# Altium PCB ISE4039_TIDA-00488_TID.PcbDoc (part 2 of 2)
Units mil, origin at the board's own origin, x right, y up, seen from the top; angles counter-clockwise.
Board outline 3000 x 2000 mil, 4 copper layers (Layer 1 - Top Layer, Layer 2 - GND, Layer 3 - PWR, Layer 4 - Bottom Layer), stack 32.634 mil thick; 131 components, 56 nets, 369 pads, 363 vias.
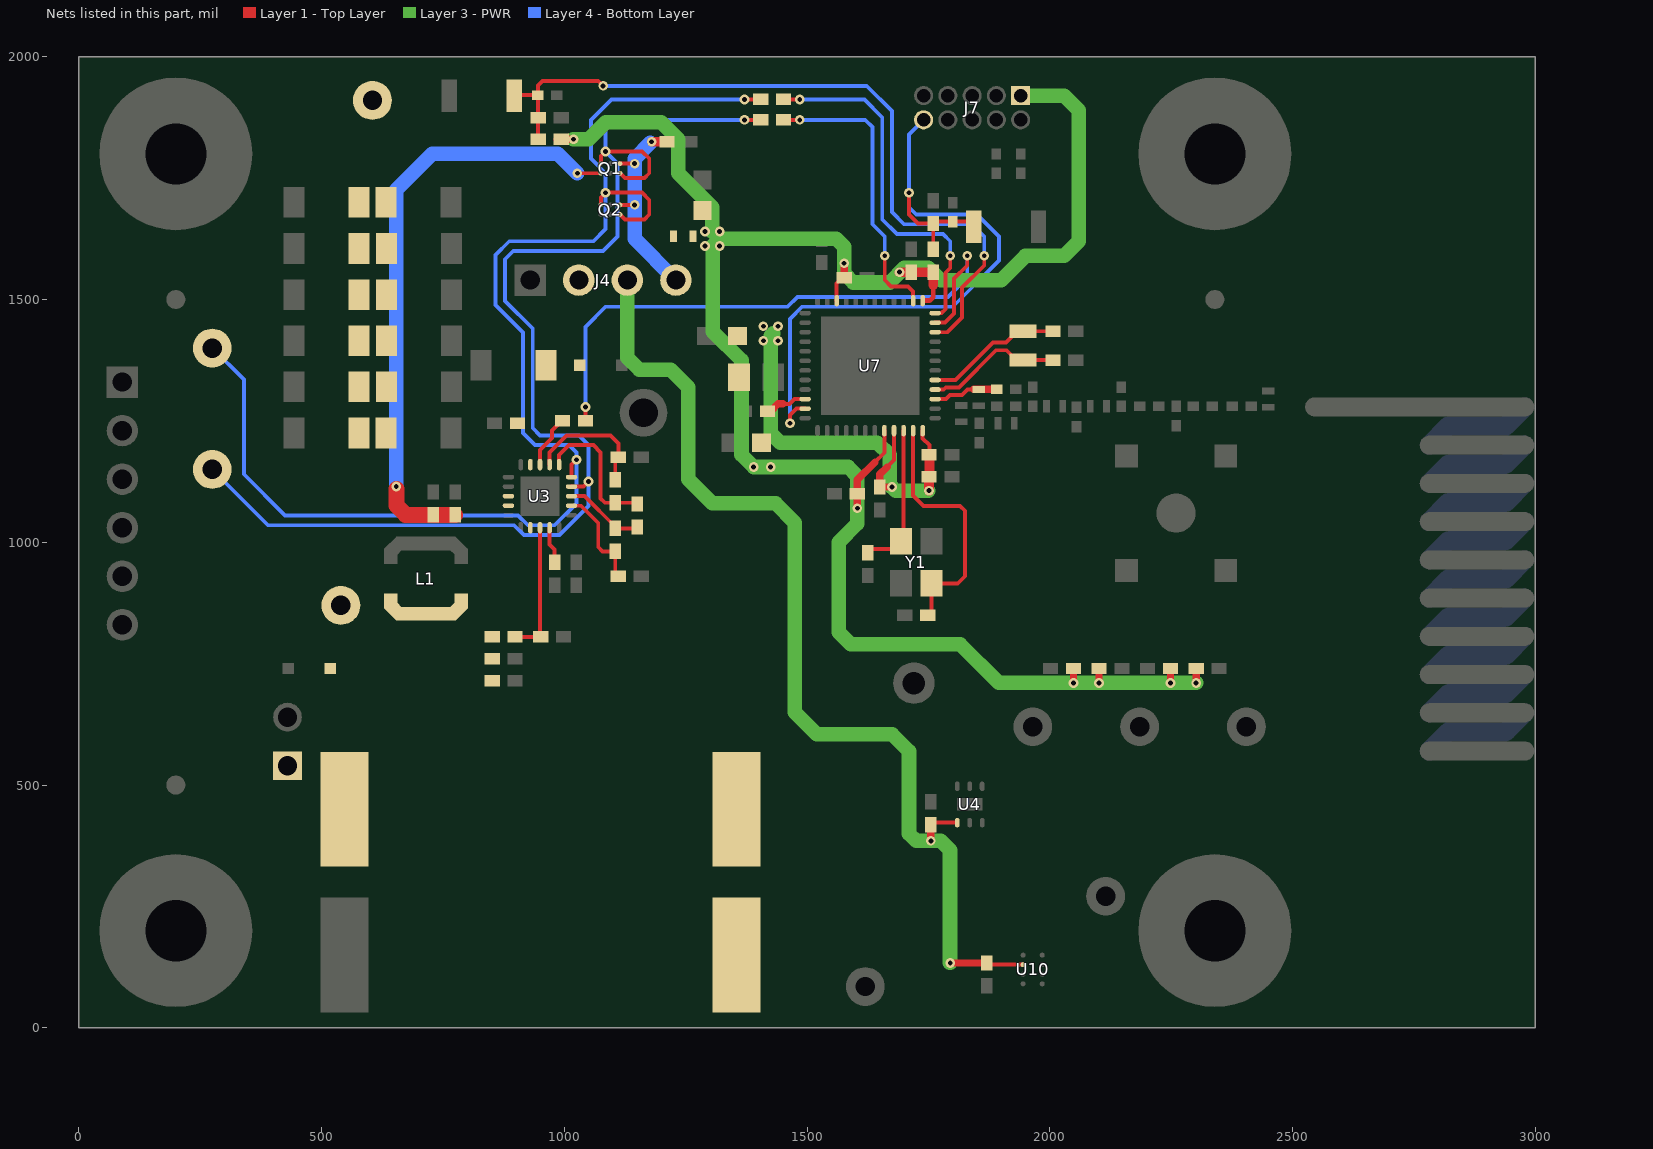
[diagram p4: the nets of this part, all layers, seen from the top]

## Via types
v1: diameter 20, hole 10, Layer 1 - Top Layer to Layer 4 - Bottom Layer, tented both sides, 323 vias
v2: diameter 19.68, hole 7.87, Layer 1 - Top Layer to Layer 4 - Bottom Layer, tented both sides, 21 vias
v3: diameter 39.37, hole 14.96, Layer 1 - Top Layer to Layer 4 - Bottom Layer, 19 vias

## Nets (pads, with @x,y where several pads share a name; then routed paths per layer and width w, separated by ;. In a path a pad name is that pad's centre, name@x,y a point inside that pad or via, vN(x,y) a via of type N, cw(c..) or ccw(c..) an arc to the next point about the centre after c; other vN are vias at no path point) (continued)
NetR1_1: R1.1 R2.2 U3.3 | length 268.3
  Layer 1 - Top Layer w8: R1.1@898.62,805 R2.2@951.38,805 R2.2@950,806.38 ; R2.2@950,816.38 U3.3@950,1030
NetR3_2: R3.2 U7.12 | length 756
  Layer 1 - Top Layer w8: R3.2@1451.62,1912 v1(1485,1912) ; U7.12@1763.74,1472.03 1777.03,1472.03 1785,1480 1785,1555 1795,1565 v1(1795,1590)
  Layer 4 - Bottom Layer w8: v1(1485,1912) 1618,1912 1655,1875 1655,1665 1685,1635 1780,1635 1795,1620 v1(1795,1590)
NetR5_2: R5.2 U3.13 | length 110.1
  Layer 1 - Top Layer w8: U3.13@950,1159.92 950,1190 975,1215 975,1230 995,1250 R5.2@996.38,1250
NetR11_2: R11.2 U7.14 | length 602
  Layer 1 - Top Layer w8: R11.2@1451.62,1870 v1(1485,1870) ; v1(1660,1590) 1660,1540 1673,1527 1708,1527 1718.46,1516.54 U7.14@1718.46,1497.62
  Layer 4 - Bottom Layer w8: v1(1485,1870) 1620,1870 1635,1855 1635,1655 1660,1630 v1(1660,1590)
NetU1_2: U1.2 U2.1
NRESET: C32.2 J7.10 R13.1 S2.2 U6.1 U7.35 | length 1429.5
  Layer 1 - Top Layer w8: v1(1465,1245) 1465,1262 1478.18,1275.18 U7.35@1496.02,1275.18 ; v1(1710,1720) 1710,1675 1728.62,1656.38 C32.2@1760,1656.38 1763.94,1660.31 U6.1@1800,1660.32 1832.76,1660.32 S2.2@1842.76,1650.32 ; R13.1@1760,1608.62 C32.2@1760,1646.38
  Layer 4 - Bottom Layer w8: v1(1465,1245) 1465,1460 1490,1485 1800,1485 1895,1580 1895,1630 1850,1675 1725,1675 1710,1690 v1(1710,1720) 1710,1840 J7.10@1740,1870
OK_HYST: R7.1 R9.2 U3.11 | length 294.6
  Layer 1 - Top Layer w8: U3.11@989.37,1159.92 989.37,1179.37 1010,1200 1060,1200 1075,1185 1075,1090 1083.62,1081.38 R9.2@1105,1081.38 1147.24,1081.38 R7.1@1150,1078.62
OK_PROG: R9.1 R10.2 U3.12 | length 256.5
  Layer 1 - Top Layer w8: U3.12@969.68,1159.92 969.68,1184.68 1005,1220 1095,1220 1111.38,1203.62 R10.2@1111.38,1175 ; R9.1@1105,1128.62 R10.2@1105,1168.62
RX_TX: C42.1 L8.1 U7.3 | length 145.8
  Layer 1 - Top Layer w8: U7.3@1763.74,1294.87 1785.87,1294.87 1794.24,1303.24 1819.16,1303.24 1830.65,1314.73 L8.1@1854,1314.73
  Layer 1 - Top Layer w15: L8.1@1843,1315 C42.1@1890.31,1315
USR_BTN: C31.2 R12.1 S1.2 U5.1 U7.10 | length 1591.5
  Layer 1 - Top Layer w8: S1.2@896.93,1920 897.93,1921 U5.1@945.63,1921 ; R12.1@945.63,1830 945.63,1874 U5.1@945.63,1921 ; v1(1080,1940) 1070,1950 955,1950 945.63,1940.63 U5.1@945.63,1921 ; U7.10@1763.74,1432.66 1789.03,1432.66 1819.5,1463.13 1819.5,1524.5 1865,1570 v1(1865,1590)
  Layer 4 - Bottom Layer w8: v1(1080,1940) 1623,1940 1675,1888 1675,1680 1700,1655 1840,1655 1865,1630 v1(1865,1590)
V_SOLAR: J1.1 U1.1
VB_PRI_ON: Q2.A2 Q2.C1 R3.1 TP5.1 U3.10 | length 2772.8
  Layer 1 - Top Layer w8: U3.10@1014.96,1134.33 1014.96,1159.96 v1(1025,1170) ; Q2.C1@1075.32,1694.84 1075.32,1710.32 v1(1085,1720) 1160,1720 1175,1705 1175,1675 1165,1665 1124.84,1665 Q2.A2@1114.68,1675.16 ; v1(1371,1912) R3.1@1404.38,1912
  Layer 4 - Bottom Layer w8: TP5.1@275,1400 340,1335 340,1140 425,1055 905,1055 925,1035 980,1035 1025,1080 v1(1025,1170) 1025,1185 1010,1200 940,1200 915,1225 915,1431.72 858,1488.72 858,1591.28 886.72,1620 1060,1620 1085,1645 v1(1085,1720) 1085,1760 1055,1790 1055,1870 1097,1912 v1(1371,1912)
VB_SEC_ON: Q1.A2 Q1.C1 R11.1 TP2.1 U3.9 | length 2554.7
  Layer 1 - Top Layer w8: U3.9@1014.96,1114.65 1039.65,1114.65 v1(1050,1125) ; Q1.C1@1075.32,1779.84 1075.32,1795.32 v1(1085,1805) 1160,1805 1175,1790 1175,1760 1165,1750 1124.84,1750 Q1.A2@1114.69,1760.16 ; v1(1371,1870) R11.1@1404.38,1870
  Layer 4 - Bottom Layer w8: TP2.1@275,1150 390,1035 896.72,1035 916.72,1015 990,1015 1050,1075 v1(1050,1125) 1050,1200 1030,1220 950,1220 935,1235 935,1440 878,1497 878,1583 895,1600 1080,1600 1110,1630 1110,1780 v1(1085,1805) 1085,1850 1105,1870 v1(1371,1870)
VBAT_OK: R5.1 U7.11 | length 1244.2
  Layer 1 - Top Layer w8: R5.1@1043.62,1250 v1(1043.62,1278.62) ; U7.11@1763.74,1452.35 1784.35,1452.35 1803,1471 1803,1543 1830,1570 v1(1830,1590)
  Layer 4 - Bottom Layer w8: v1(1043.62,1278.62) 1043.62,1443.62 1085,1485 1460,1485 1480,1505 1790,1505 1830,1545 v1(1830,1590)
VBAT_OV: R6.1 R8.2 U3.7 | length 208.2
  Layer 1 - Top Layer w8: U3.7@1014.96,1075.28 1034.72,1075.28 1070,1040 1070,990 1078.62,981.38 R6.1@1105,981.38 R8.2@1105,931.38
VBAT_PRI: C18.1 C48.1 D2.1 J4.2 U3.14
VBAT_SEC: C6.1 C7.1 C8.1 C9.1 C10.1 C11.1 C12.1 C13.1 C14.1 C15.1 C16.1 C17.1 TP3.1 U3.18
VDD_3P3: C20.2 C43.2 J4.3 L2.2 U4.1 U10.B1 | length 2156.8
  Layer 1 - Top Layer w8: C20.2@1755.6,422.6 U4.1@1809.41,422.6 ; C43.2@1870,133.62 1870,129.69 1870.31,130 U10.B1@1945,130
  Layer 1 - Top Layer w15: v1(1755,385) C20.2@1755,418.38 ; v1(1795,133.62) C43.2@1870,133.62
  Layer 3 - PWR w30: J4.3@1130,1540 1130,1380 1155,1355 1219.4,1355 1255,1319.4 1255,1130 1305,1080 1435,1080 1475,1040 1475,650 1520,605 1675,605 1710,570 1710,400 1725,385 v1(1755,385) 1775,385 1794.51,365.49 v1@1794.51,133.62
VDD_3P3_SW: C19.1 J4.4 Q1.A1 Q2.A1 | length 423.2
  Layer 1 - Top Layer w8: Q2.A1@1114.68,1694.84 v1(1145,1694.84) ; Q1.A1@1114.69,1779.84 v1(1145,1779.84)
  Layer 1 - Top Layer w20: v1(1180,1825) C19.1@1211.38,1825
  Layer 4 - Bottom Layer w30: v1@1177.5,1822.5 1145,1790 v1(1145,1779.84) v1(1145,1694.84) 1145,1625 J4.4@1230,1540
VDDR: C27.1 C28.1 C29.1 C30.1 L3.2 U7.45 U7.48 | length 890.5
  Layer 1 - Top Layer w8: 1665,1155 1679.09,1169.09 U7.45@1679.09,1229.91 ; U7.48@1738.15,1229.91 1738.15,1213.85 1752,1200 C29.1@1752,1184.32
  Layer 1 - Top Layer w15: 1665,1155 1650,1140 C28.1@1650,1113.62 v1(1675,1113.62)
  Layer 1 - Top Layer w20: v1(1751.38,1106.32) C30.1@1751.38,1135 ; C30.1@1752.38,1140 C29.1@1752.38,1180
  Layer 3 - PWR w30: 1430,1430 1425,1425 1425,1225 1445,1205 1645,1205 1670,1180 1670,1118.62 v1(1675,1113.62) 1682.31,1106.32 v1@1750,1106.32
  other v1: 1410,1415 1440,1415 1410,1445 1440,1445
VDDS: C21.1 C22.1 C23.1 C24.1 C25.1 C26.1 J7.1 L2.1 R12.2 R13.2 R14.2 R15.2 R16.2 R17.2 U7.13 U7.22 U7.34 U7.44 | length 4254
  Layer 1 - Top Layer w8: 1450,1285 1464,1285 1473.87,1294.87 U7.34@1496.02,1294.87 ; U7.22@1560.98,1497.62 1560.98,1532.98 C23.1@1573,1545 ; 1640,1165 1659.41,1184.41 U7.44@1659.41,1229.91
  Layer 1 - Top Layer w10: U7.13@1740,1497.62 1752.62,1497.62 1760,1505 1760,1530
  Layer 1 - Top Layer w15: R12.2@985,1830 R12.2@993.94,1830 v1(1019,1830) ; C26.1@1419.69,1270 1425,1270 1440,1285 1450,1285 ; C23.1@1573,1545 C23.1@1576.38,1545 v1(1576.38,1574.68) ; v1(1603.62,1070) C24.1@1603.62,1100 1603.62,1128.62 1640,1165 ; v1(2048.62,710.31) R14.2@2048.62,740 ; v1(2101.38,710.31) R16.2@2101.38,740 ; v1(2248.62,710.31) R15.2@2248.62,740 ; v1(2301.38,710.31) R17.2@2301.38,740
  Layer 1 - Top Layer w20: v1(1690.31,1556.38) C22.1@1715,1556.38 R13.2@1760,1556.38 1760,1530
  Layer 3 - PWR w30: v1(1019,1830) 1050,1830 1085,1865 1200,1865 1235,1830 1235,1760 1305,1690 1305,1640 1320,1625 ; J7.1@1940,1920 2030,1920 2060,1890 2060,1620 2030,1590 1950,1590 1900,1540 1775,1540 1750,1565 1700,1565 1670,1535 1595,1535 1576.38,1553.62 v1(1576.38,1574.68) 1576.38,1608.62 1560,1625 1320,1625 ; v1(2301.38,710.31) v1(2248.62,710.31) v1(2101.38,710.31) v1(2048.62,710.31) 1894.69,710.31 1815,790 1590,790 1565,815 1565,1000 1603.62,1038.62 v1(1603.62,1070) 1603.62,1136.38 1585,1155 v1(1425,1155) v1(1390,1155) 1365,1180 1365,1375 1306,1434 1306,1611 1320,1625
  other v1: 1290,1610 1320,1610 1290,1640 1320,1640
VIN_BQ: C1.1 C4.1 D1.1 L1.1 R1.2 TP1.1 U3.2
VRDIV: R6.2 R7.2 U3.8 | length 161.7
  Layer 1 - Top Layer w8: U3.8@1014.96,1094.96 1042.04,1094.96 1105,1032 R6.2@1105,1028.62 R7.2@1147.24,1028.62
VREF_SAMP: C5.1 U3.4 | length 75.7
  Layer 1 - Top Layer w8: U3.4@969.68,1030 969.68,995.32 980,985 C5.1@980,958.62
VSTOR: C2.1 C3.1 Q1.C2 U3.19 | length 1242.9
  Layer 1 - Top Layer w8: v1(1027,1760) 1075.16,1760 Q1.C2@1075.32,1760.16
  Layer 1 - Top Layer w33: v1@654,1110 654,1076 673.5,1056.5 ; 673.62,1056.38 673.5,1056.5 ; C3.1@775,1056.5 673.5,1056.5
  Layer 4 - Bottom Layer w30: v1(654,1115) 654,1726 728,1800 987,1800 v1(1027,1760)
X24M_N: C45.1 U7.46 Y1.3 | length 298.2
  Layer 1 - Top Layer w8: C45.1@1625,978.62 1632.87,986.5 1677.93,986.5 Y1.3@1693.5,1002.07 Y1.3@1698.78,1007.35 ; Y1.3@1698.78,1017.35 U7.46@1698.78,1229.91
X24M_P: C44.1 U7.47 Y1.1 | length 528
  Layer 1 - Top Layer w8: U7.47@1718.46,1229.91 1718.46,1096.54 1740,1075 1815,1075 1825,1065 1825,930 1810.46,915.46 Y1.1@1756.5,915.46 C44.1@1756.5,850
X32K_Q1: C47.2 U7.4 Y2.1 | length 285.8
  Layer 1 - Top Layer w8: U7.4@1763.74,1314.55 1781.55,1314.55 1785.74,1318.74 1812.74,1318.74 1889.47,1395.47 1910.53,1395.47 1930.53,1375.47 Y2.1@1945,1375.47 C47.2@2006.38,1375.47 ; Y2.1@1943.65,1374.13 Y2.1@1945,1374.47
X32K_Q2: C46.2 U7.5 Y2.2 | length 284.8
  Layer 1 - Top Layer w8: U7.5@1763.74,1334.24 1805.49,1334.24 1882.72,1411.47 1909.47,1411.47 1932.53,1434.53 Y2.2@1934.53,1434.53 ; Y2.2@1935,1435 Y2.2@1934.53,1434.53 ; C46.2@2006.38,1434.53 Y2.2@1945,1434.53 Y2.2@1934.53,1434.53
pads on no net: FID1.1 FID2.1 FID3.1 J7.6 J7.7 J7.8 Q1.B1 Q1.B2 Q2.B1 Q2.B2 SH-J1.0 SH-J2.0 SH-J3.0 SH-J4.0 SH-J5.0 U7.15 U7.16 U7.17 U7.18 U7.19 U7.20 U7.21 U7.26 U7.27 U7.28 U7.29 U7.30 U7.31 U7.32 U7.36 U7.37 U7.38 U7.39 U10.C2

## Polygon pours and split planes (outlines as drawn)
GND on Layer 2 - GND "Layer 2 - GND- GND" (solid, remove dead copper, pour order 2): 20,20 2525,20 2525,1980 20,1980
GND on Layer 3 - PWR "Layer 3 - PWR- GND" (solid, remove dead copper, pour order 4): 20,20 2525,20 2525,1980 20,1980
GND on Layer 4 - Bottom Layer "Layer 4 - Bottom Layer- GND" (solid, remove dead copper, pour order 6): 20,20 2525,20 2525,1980 20,1980
GND on Layer 1 - Top Layer "Layer 1 - Top Layer- GND" (solid, remove dead copper, pour order 8): 20,20 2525,20 2525,1980 20,1980

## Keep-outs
Keep-Out Layer:
  text ".Layer_Name" at 582,-858.49 h60

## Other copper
Layer 1 - Top Layer:
  pour cut-out: 1040,1640 1065,1640 1065,1745 1040,1745
  pour cut-out: 1364.71,1148.19 1364.71,1104 1436,1104 1436,1148.19
  region net VSTOR: 897,1070 897,1080 799,1080 792,1073 715,1073 715,1040 800,1040 830,1070
  region net GND: 1690,1900 1760,1900 1760,1970 1690,1970
  region net GND: 1820,1970 1820,1900 1910,1900 1910,1970
  pour cut-out: 1998.5,715.16 1998.5,635 2120,635 2120,715
  pour cut-out: 1770,380 1895,380 1895,510 1770,510
  pour cut-out: 1605,965 1605,945 1720,945 1720,830 1725,830 1725,965
  pour cut-out: 1725,1060 1810,1060 1810,945 1725,945
  pour cut-out: 885,1030 1015,1030 1015,1160 885,1160
  pour cut-out: 1495,1230 1765,1230 1765,1554 1495,1554
  pour cut-out: 1700,1806 1980,1806 1980,1961.93 1700,1961.93
  pour cut-out: 880,1490 1280,1490 1280,1560 1250,1590 880,1590
  pour cut-out: 40,880 140,880 140,1280 40,1280
  pour cut-out: 384.68,494.31 475.68,494.31 475.68,686.31 474.68,685.31 384.68,685.31
  pour cut-out: 1840,0 2065,0 2065,205 1840,205
  region net GND: 2525,1305 2475,1305 2475,1980 2525,1980
  region net GND: 2475,20 2475,1240 2525,1240 2525,20
  pour cut-out: 2525,2000 3000,2000 3000,0 2525,0
  region net NetD1_2: 465,605 395,605 395,750 410,765 450,765 465,750
  region net VIN_BQ: 495,685 495,895 520,920 835,920 925,1010 925,1042 936,1042 936,896 868,828 868,685
  region net LBOOST: 625,955 805,955 897,1047 897,1061 835,1061 794,1020 650,1020 625,995
  region net VBAT_SEC: 535,1950 510,1925 510,1160 530,1140 794,1140 844,1090 897,1090 897,1100 868,1100 798,1170 725,1170 700,1195 700,1925 675,1950
  region net GND: 470,1665 385,1665 385,1735 470,1735
  region net GND: 470,1570 385,1570 385,1640 470,1640
  region net GND: 470,1475 385,1475 385,1545 470,1545
  region net GND: 470,1380 385,1380 385,1450 470,1450
  region net GND: 470,1285 385,1285 385,1355 470,1355
  region net GND: 470,1190 385,1190 385,1260 470,1260
  region net GND: 876,1109 800,1185 740,1185 725,1200 725,1735 730,1740 825,1740 873,1692 873,1217 916,1174 916,1143 925,1134 925,1103 910,1103 904,1109
  region net NetBT1_1: 1145,1215 1095,1265 1095,1385 1185,1385 1220,1350 1220,1250 1185,1215
  region net VBAT_PRI: 1065,1560 1050,1575 1010,1575 995,1560 995,1495 978,1478 905,1478 887,1460 887,1223 925,1185 925,1148 936,1148 936,1201 960,1225 960,1265 975,1280 1010,1280 1065,1335
  region net NetU1_2: 1507,575 1507,25 1302,25 1302,575
  region net VDDS: 1380,1233 1380,1145 1435,1145 1435,1235 1435,1282 1402,1282 1402,1255
  region net GND: 1285,1265 1285,1175 1367.09,1175 1367.09,1237.09 1388,1258 1388,1295 1315,1295
  region net DCDC_SW: 1508,1309 1405,1309 1405,1370 1460,1370 1470,1360 1470,1330 1480,1320 1508,1320
  region net GND: 1730,970 1795,970 1805,980 1805,1050 1800,1055 1740,1055 1730,1045
  region net GND: 1605,950 1720,950 1720,830 1605,830
  region net GND: 785,1960 720,1960 720,1880 785,1880
  region net GND: 1955,1610 2020,1610 2020,1690 1955,1690
  region net VDDS: 1255,1605 1265,1595 1325,1595 1335,1605 1335,1700 1325,1710 1265,1710 1255,1700
  region net VDD_3P3: 1150,1505 1170,1525 1170,1570 1195,1595 1225,1595 1235,1605 1235,1645 1170,1645 1145,1645 1090,1590 1090,1565 1090,1525 1110,1505
  region net GND: 1265,1730 1256.46,1738.54 1256.46,1781.46 1265,1790 1360,1790 1370,1780 1370,1740 1360,1730
  region net GND: 1314,1390 1230,1390 1230,1460 1314,1460
  region net VDDR: 1385,1310 1385,1380 1400,1395 1440,1395 1455,1410 1455,1445 1440,1460 1330,1460 1330,1310
  pour cut-out: 866.18,1969 955,1969 955,1960 866.18,1960
  region net V_SOLAR: 605,575 605,325 460,325 395,390 395,575
  region net GND: 605,30 415,30 415,270 605,270
  pour cut-out: 1598.19,1009.37 1598.19,1068.19 1620,1090 1685,1090 1685,1030 1664.37,1009.37
  pour cut-out: 2150,820.49 2245,820.49 2250,815.49 2250,800 2150,800
  pour cut-out: 605,935 605,1136 630,1136 630,935
  pour cut-out: 1990,1349 2037.13,1349 2037.13,1480 1990,1480
  pour cut-out: 1780,1200 1840,1200 1840,1210 1955,1210 1955,1250 2525,1250 2525,1260 1940,1260 1940,1225 1780,1225
  region net GND: 1840,1218 1956,1218 1956,1209 1840,1209
  pour cut-out: 2525,1305 1915,1305 1915,1310 2525,1310
  region net GND: 1917.13,1317.07 1917.13,1305 2525,1305 2520,1310 2515,1310 2507.93,1317.07
  pour cut-out: 1951.37,1589.37 1885,1589.37 1885,1575 1951.37,1575
  text ".Layer_Name" at 582,-858.49 h60
Layer 2 - GND:
  pour cut-out: 384.68,494.31 475.68,494.31 475.68,686.31 474.68,685.31 384.68,685.31
  pour cut-out: 40,880 140,880 140,1280 40,1280
  pour cut-out: 880,1490 1280,1490 1280,1560 1250,1590 880,1590
  region net GND: 1820,1970 1820,1900 1910,1900 1910,1970
  region net GND: 1690,1900 1760,1900 1760,1970 1690,1970
  pour cut-out: 1700,1828.07 1980,1828.07 1980,1961.93 1700,1961.93
  pour cut-out: 1840,0 2065,0 2065,205 1840,205
  region net GND: 2525,1305 2475,1305 2475,1980 2525,1980
  region net GND: 2475,20 2475,1240 2525,1240 2525,20
  text ".Layer_Name" at 582,-858.49 h60
Layer 3 - PWR:
  pour cut-out: 1700,1828.07 1980,1828.07 1980,1961.93 1700,1961.93
  region net GND: 1690,1900 1760,1900 1760,1970 1690,1970
  region net GND: 1820,1970 1820,1900 1910,1900 1910,1970
  pour cut-out: 880,1490 1280,1490 1280,1590 880,1590
  pour cut-out: 40,880 140,880 140,1280 40,1280
  pour cut-out: 384.68,494.31 475.68,494.31 475.68,686.31 474.68,685.31 384.68,685.31
  pour cut-out: 1840,0 2065,0 2065,205 1840,205
  region net GND: 2525,1305 2475,1305 2475,1980 2525,1980
  region net GND: 2475,20 2475,1240 2525,1240 2525,20
  region net VDDS: 1320,1595 1290,1595 1275,1610 1275,1640 1290,1655 1320,1655 1335,1640 1335,1610
  region net VDDR: 1440,1400 1410,1400 1395,1415 1395,1445 1410,1460 1440,1460 1455,1445 1455,1415
  pour cut-out: 1215,1754 1099,1754 1060,1793 1060,1810 1095,1845 1215,1845
  pour cut-out: 2349.37,725 2349.37,770 2335,770 2335,725
  text ".Layer_Name" at 582,-858.49 h60
Layer 4 - Bottom Layer:
  region net GND: 1820,1970 1820,1900 1910,1900 1910,1970
  region net GND: 1690,1900 1760,1900 1760,1970 1690,1970
  pour cut-out: 384.68,494.31 475.68,494.31 475.68,686.31 474.68,685.31 384.68,685.31
  pour cut-out: 40,880 140,880 140,1280 40,1280
  pour cut-out: 880,1490 1280,1490 1280,1560 1250,1590 880,1590
  pour cut-out: 1700,1828.07 1980,1828.07 1980,1961.93 1700,1961.93
  pour cut-out: 1840,0 2065,0 2065,205 1840,205
  region net GND: 2525,1305 2475,1305 2475,1980 2525,1980
  region net GND: 2475,20 2475,1240 2525,1240 2525,20
  pour cut-out: 1635,1520 1805,1520 1805,1630 1635,1630
  pour cut-out: 1371,1844.51 1485,1844.51 1485,1925 1371,1925
  pour cut-out: 1004.43,1755.2 1004.43,1630 1060,1630 1060,1754.89
  pour cut-out: 2349.37,725 2349.37,775 2330,775 2330,725
  pour cut-out: 2223.13,710.31 2223.13,765.89 2350,765.89 2350,709.67
  pour cut-out: 1069.11,1278.62 1069.37,1200 1050,1200 1035,1215 1035,1278.62
  text ".Layer_Name" at 582,-858.49 h60

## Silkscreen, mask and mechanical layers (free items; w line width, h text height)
Top Overlay:
  circle w10: c1908,150 r2.24
  circle w10: c1809,394 r2.24
  circle w10: c1809,1217 r2.24
  circle w10: c910,993 r2.24
  text "VBAT" at 515,1750 h75
  text "USR" at 760,1750 h75
  text "RESET" at 1800,1495 h75
  text "PRI ON" at 185,1245 h60
  text "SEC ON" at 180,995 h60
  text "VIN" at 350,820 h75
  text ".tid" at 1149.8,688.55 h85
  text ".PRJ_Number" at 1150,615 h85
  text ".SCH_Rev" at 1475,615 h85
  text "GND" at 1690,45 h75
  text ".Layer_Name" at 582,-858.49 h60
Bottom Overlay:
  text ".Layer_Name" at 582,-858.49 h60
Top Paste:
  text ".Layer_Name" at 582,-858.49 h60
Bottom Paste:
  text ".Layer_Name" at 582,-858.49 h60
Top Solder:
  text ".Layer_Name" at 582,-858.49 h60
  text ".Layer_Name" at 582,-858.49 h60
Bottom Solder:
  text ".Layer_Name" at 582,-858.49 h60
Drill Guide:
  text ".Layer_Name" at 582,-858.49 h60
M1 Board Outline:
  lines w20: -10,0 ccw(c0,0) 0,-10 ; -10,0 ccw(c0,0) 0,-10 ; -10,0 -10,2000 ; -10,2000 cw(c0,2000) 0,2010 ; -10,2000 cw(c0,2000) 0,2010 ; 0,-10 3000,-10 ; 0,2010 3000,2010 ; 3000,-10 ccw(c3000,0) 3010,0 ; 3000,-10 ccw(c3000,0) 3010,0 ; 3000,2010 cw(c3000,2000) 3010,2000 ; 3000,2010 cw(c3000,2000) 3010,2000 ; 3010,0 3010,2000
  text ".Layer_Name" at 582,-858.49 h60
M2 Board Dimensions:
  rectangle: 130,-400 505,-275
  rectangle: 5,-275 130,-150
  lines w7: 5,-275 1005,-275 ; 130,-400 130,-150 ; 255,-400 255,-150 ; 505,-400 505,-150 ; 755,-400 755,-150 ; 5,-400 5,-150 1005,-150 1005,-400 5,-400
  text ".Layer_Name" at 582,-858.49 h60
M3 3D STEP Top:
  text ".Layer_Name" at 582,-858.49 h60
M4 3D STEP Bottom:
  text ".Layer_Name" at 582,-858.49 h60
M5 Assembly Top:
  lines w10: -287,-930.17 6313,-930.17 ; -287,-726.83 6315,-726.83 ; -287,-523.5 -287,-1133.5 3718,-1133.5 6315,-1133.5 6315,-523.5 -286.5,-523.5 -286.5,-1133.5 1289,-1133.5 ; 2178,-1133.5 2178,-523.5 ; 3445,-726.83 3445,-523.5 ; 4285,-726.83 4285,-523.5 ; 4907,-1140 4907,-937.17
  text "COMPONENTS MARKED 'DNP' SHOULD NOT BE POPULATED." at 1158.5,-318.5 h60
  text "ASSEMBLY VARIANT:" at 1158,-434 h60
  text ".VariantName" at 2194,-434 h60
  text "PCB VIEWED FROM TOP SIDE" at -223.5,-655.67 h60
  text "BOARD #:" at 2253,-655.67 h60
  text ".PRJ_Number" at 2798.5,-655.67 h60
  text "REV:" at 3643,-655.67 h60
  text ".PCB_Rev" at 3934.5,-655.67 h60
  text "SVN REV:" at 4481,-655.67 h60
  text ".VersionControl_RevNumber" at 4987,-655.67 h60
  text "TID #:" at 2253,-859 h60
  text ".TID" at 2798.5,-859 h60
  text "PLOT NAME =" at -223.5,-1064.34 h60
  text ".plot_File_Name" at 582,-1064.34 h60
  text "GENERATED    :" at 2255,-1064.34 h60
  text ".Print_Date" at 3124.5,-1064.34 h60
  text ".Print_Time" at 3853.5,-1064.34 h60
  text "TEXAS INSTRUMENTS" at 5118,-1064.34 h60
M6 Assembly Bottom:
  lines w10: -287.5,-727.33 6314.5,-727.33 ; -285.5,-930.67 6314.5,-930.67 ; 1120.5,-1140.5 1120.5,-937.67 ; 1742.5,-727.33 1742.5,-524 ; 2582.5,-727.33 2582.5,-524 ; 3849.5,-1134 3849.5,-524 ; 4738.5,-1134 6314,-1134 6314,-524 -287.5,-524 -287.5,-1134 2309.5,-1134 6314.5,-1134 6314.5,-524
  text "COMPONENTS MARKED 'DNP' SHOULD NOT BE POPULATED." at 6107,-318 h60
  text ".VariantName" at 5063,-434 h60
  text "ASSEMBLY VARIANT:" at 6102,-434 h60
  text ".VersionControl_RevNumber" at 1040.5,-656.17 h60
  text "SVN REV:" at 1546.5,-656.17 h60
  text ".PCB_Rev" at 2093,-656.17 h60
  text "REV:" at 2384.5,-656.17 h60
  text ".PRJ_Number" at 3229,-656.17 h60
  text "BOARD #:" at 3774.5,-656.17 h60
  text "PCB VIEWED FROM BOTTOM SIDE" at 6251,-656.17 h60
  text ".TID" at 3229,-859.5 h60
  text "TID #:" at 3774.5,-859.5 h60
  text "TEXAS INSTRUMENTS" at 909.5,-1064.84 h60
  text ".Print_Time" at 2174,-1064.84 h60
  text ".Print_Date" at 2903,-1064.84 h60
  text "GENERATED    :" at 3772.5,-1064.84 h60
  text ".plot_File_Name" at 5445.5,-1064.84 h60
  text "PLOT NAME =" at 6251,-1064.84 h60
M9 Title Sheet:
  drawing of 1178 lines, arcs and shapes, not listed
  text "1" at 744.84,8036.5 h70
  text "2" at 3240.5,8036.5 h70
  text "3" at 5729.84,8036.5 h70
  text "4" at 8236.51,8036.5 h70
  text "5" at 10735.5,8036.5 h70
  text "6" at 13240.5,8036.5 h70
  text "A" at -411.5,6893.5 h70
  text "A" at 14388.5,6893.5 h70
  text "B" at -411.5,4513.5 h70
  text "B" at 14388.5,4513.5 h70
  text "C" at -411.5,2138.5 h70
  text "C" at 14388.5,2138.5 h70
  text "PROJECT TITLE:" at 11348.5,277.5 h45
  text ".PRJ_Title" at 11398.5,144.17 h70
  text "DESIGNED FOR:" at 11348.5,-23.5 h45
  text ".PRJ_Customer" at 11398.5,-163.5 h70
  text "D" at -411.5,-231.5 h70
  text "D" at 14388.5,-231.5 h70
  text "FILE NAME:" at 11348.5,-323.5 h45
  text ".PCB_File_Name_No_Path" at 11398.5,-443.5 h70
  text "Texas Instruments (TI) and/or its licensors do not warrant the accuracy or completeness of this specification" at 6379,-605.34 h45
  text "ENGINEER:" at 11348.5,-613.5 h45
  text "LAYOUT BY:" at 12853.5,-613.5 h45
  text "or any information contained therein. TI and/or its licensors do not warrant that this design will meet" at 6334.02,-718 h45
  text ".PRJ_Engineer" at 11398.5,-768.49 h70
  text ".PCB_Layout" at 12904,-768.49 h70
  text "JMM" at 12856,-801 h100
  text "s  o  l  u  t  i  o  n  s" at 13714,-804 h68
  text "the specifications, will be suitable for your application or fit for any particular purpose, or will operate in" at 6334.02,-830.67 h45
  text ".Layer_Name" at 582,-858.49 h60
  text "ALTIUM DESIGNER VERSION:" at 12853.5,-923.5 h45
  text "an implementation. TI and/or its licensors do not warrant that the design is production worthy. You should" at 6334.02,-943.33 h45
  text "completely validate and test your design implementation to confirm the system functionality for your application." at 6379,-1056 h45
  text ".print_Scale" at 11398.5,-1056.83 h70
  text ".Application_BuildNumber" at 12904,-1056.83 h70
  text "1" at 744.84,-1263.5 h70
  text "2" at 3240.5,-1263.5 h70
  text "3" at 5729.84,-1263.5 h70
  text "4" at 8236.51,-1263.5 h70
  text "5" at 10735.5,-1263.5 h70
  text "6" at 13240.5,-1263.5 h70
M10 Fab Notes:
  drawing of 186 lines, arcs and shapes, not listed
  text "DESIGN INFORMATION" at 12386.02,5910 h60
  text "MIN. TRACK WIDTH:" at 11741.46,5730 h60
  text "8" at 12837.7,5730 h60
  text "MIL" at 12992.46,5730 h60
  text "MIN. CLEARANCE:" at 11741.46,5598 h60
  text "0.2" at 12777.7,5598 h60
  text "mm" at 12992.46,5598 h60
  text "MIN. VIA PAD SIZE:" at 11741.46,5466 h60
  text "20" at 12807.71,5466 h60
  text "MIL" at 12992.46,5466 h60
  text "0.05mm (2MIL)" at 12436.46,5324.29 h60
  text "MINIMUM ANNULAR RING" at 11412.23,5320 h60
  text "EXTERNAL" at 13144.46,5320 h60
  text "PER" at 11612.23,5202 h60
  text "IPC-D-275 CLASS 2 LEVEL C" at 11832.23,5202 h60
  text "MIL, HOLES" at 13320.46,5089.71 h60
  text "+/-" at 12928,5089 h60
  text "+/-" at 13782,5089 h60
  text "REGISTRATION TOLERANCES:" at 11412.23,5084 h60
  text "METAL" at 12612,5084 h60
  text "5" at 13188.2,5084 h60
  text "3" at 14021.2,5084 h60
  text "MIL" at 14137.46,5084 h60
  text "MATERIAL:" at 11337.46,4874.54 h60
  text "Impedance Control:" at 6645,4840 h200
  text "FR-4 High Tg" at 12323.9,4734.21 h60
  text "FR-408" at 11758.46,4725.64 h60
  text "X" at 12170.46,4725.64 h60
  text "OTHER" at 13246.46,4725.64 h60
  text "- Top layer contains 50 ohm impedance (+/- 10%) single ended using 15 mil traces (from E1 to U7)" at 6645,4600 h100
  text "62 MIL (1.6mm) +/-10%" at 12078.56,4562.92 h60
  text "33 MIL" at 13805,4560 h60
  text "THICKNESS:" at 11412.23,4558.64 h60
  text "OTHER" at 13363.46,4558.64 h60
  text "X" at 13237,4554 h60
  text "TOLERANCE:" at 11412.23,4400.64 h60
  text "X" at 12251.54,4400.64 h60
  text "ANSI IPC-6012 TYPE 3 CLASS 2" at 12438.48,4400.64 h60
  text "OTHER +/-" at 12438.46,4244.64 h60
  text "BOW & TWIST:" at 11412.23,4087.64 h60
  text "X" at 12251.54,4087.64 h60
  text "ANSI IPC-6012 TYPE 3 CLASS 2" at 12438.48,4087.64 h60
  text "OTHER +/-" at 12438.46,3929.13 h60
  text "DRILLING:" at 11337.46,3790.64 h60
  text "REFERENCE:" at 11412.23,3673.64 h60
  text "X" at 12060.46,3673.64 h60
  text "AS SHOWN" at 12247.46,3673.64 h60
  text "X" at 12961.46,3673.64 h60
  text "NC_DRILL FILES" at 13098.46,3673.64 h60
  text "PTH MIN COPPER THICKNESS:" at 11412.23,3515.64 h60
  text "X" at 12762.46,3515.64 h60
  text "1MIL" at 12899.46,3515.64 h60
  text "OTHER" at 13396.46,3515.64 h60
  text "BOARD FINISH:" at 11337.46,3356.64 h60
  text "SILKSCREEN:" at 11492.68,3238.64 h60
  text "X" at 12441.46,3238.64 h60
  text "TOP" at 12567.46,3238.64 h60
  text "X" at 12951.46,3238.64 h60
  text "BOTTOM" at 13078.46,3238.64 h60
  text "SILKSCREEN COLOR:" at 11492.68,3071.64 h60
  text "X" at 12440.42,3071.64 h60
  text "WHITE" at 12567.46,3071.64 h60
  text "OTHER" at 13078.46,3071.64 h60
  text "SOLDER RESIST COLOR:" at 11492.68,2901.64 h60
  text "X" at 12063.98,2742.13 h60
  text "GREEN" at 12187.46,2742.44 h60
  text "BLUE" at 12778.46,2742.44 h60
  text "OTHER" at 13316.46,2742.44 h60
  text "IMMERSION GOLD (ENIG)" at 12398.46,2553.92 h60
  text "ENEPIG" at 13736,2550.64 h60
  text "SURFACE FINISH:" at 11337.46,2549.64 h60
  text "X" at 12211.51,2549.64 h60
  text "IMM. TIN/SILVER OR EQUIV" at 11667,2392.64 h60
  text "OTHER" at 13098.46,2392.64 h60
  text "ARRAY/PANEL:" at 11337.46,2213.64 h60
  text "CUT AND TRIM PER MECH LAYER 1" at 12398.46,2209.35 h60
  text "N.C. ROUTE" at 12398.46,2057.64 h60
  text "X" at 13077.46,2057.64 h60
  text "V. SCORE" at 13264.46,2057.64 h60
  text "CERTIFICATION:" at 11337.46,1920.64 h60
  text "MATERIALS AND WORKMANSHIP FOR ALL PCBS" at 12062.46,1920.64 h60
  text "TO MEET OR EXCEED THE REQUIREMENTS OF:" at 12062.46,1822.64 h60
  text "X" at 11688.96,1686.13 h60
  text "ANSI IPC-A-600F CLASS ->" at 11827.96,1686.13 h60
  text "X" at 13467.02,1686.13 h60
  text "2" at 13585.96,1686.14 h60
  text "1" at 13270.96,1684.64 h60
  text "3" at 13939.96,1684.64 h60
  text "X" at 11691.02,1526.64 h60
  text "UL 94V-0" at 11827.96,1526.64 h60
  text "X" at 12503.02,1526.64 h60
  text "RoHS" at 12639.96,1526.64 h60
  text "OTHER" at 13284.37,1526.64 h60
  text "PER ORDER" at 13681.42,1526.64 h60
  text "ADDITIONAL REQUIREMENTS:" at 11337.46,1385.64 h60
  text "MICROSECTION:" at 11412.23,1270.64 h60
  text "YES" at 12317.96,1270.64 h60
  text "REQUIRED" at 13179.46,1114.49 h60
  text "BARE BOARD ELEC. TEST:" at 11412.23,1111.64 h60
  text "NONE" at 12717.96,1111.64 h60
  text "X" at 13052.46,1111.64 h60
  text "PER ORDER" at 13771.46,1111.64 h60
  text "MANUFACTURER'S UL:" at 11412.23,954.64 h60
  text "RAIL" at 12577.96,950.35 h60
  text "METAL" at 13069.78,950.35 h60
  text "X" at 13445,950 h60
  text "SILK" at 13581.46,950.35 h60
  text ".Layer_Name" at 582,-858.49 h60
M11 Gerber Information:
  lines w10: -287,-930.17 6313,-930.17 ; -287,-726.83 6315,-726.83 ; -287,-523.5 -287,-1133.5 3718,-1133.5 6315,-1133.5 6315,-523.5 -286.5,-523.5 -286.5,-1133.5 1289,-1133.5 ; 2178,-1133.5 2178,-523.5 ; 3445,-726.83 3445,-523.5 ; 4285,-726.83 4285,-523.5 ; 4907,-1140 4907,-937.17
  text "ALL ARTWORK VIEWED FROM TOP SIDE" at -223.5,-655.67 h60
  text "BOARD #:" at 2253,-655.67 h60
  text ".PRJ_Number" at 2798.5,-655.67 h60
  text "REV:" at 3643,-655.67 h60
  text ".PCB_Rev" at 3934.5,-655.67 h60
  text "SVN REV:" at 4481,-655.67 h60
  text ".VersionControl_RevNumber" at 4987,-655.67 h60
  text "LAYER NAME =" at -223.5,-858.49 h60
  text "TID #:" at 2253,-859 h60
  text ".TID" at 2798.5,-859 h60
  text "PLOT NAME =" at -223.5,-1064.34 h60
  text ".plot_File_Name" at 582,-1064.34 h60
  text "GENERATED    :" at 2255,-1064.34 h60
  text ".Print_Date" at 3124.5,-1064.34 h60
  text ".Print_Time" at 3853.5,-1064.34 h60
  text "TEXAS INSTRUMENTS" at 5118,-1064.34 h60
M12 Stackup:
  drawing of 527 lines, arcs and shapes, not listed
  text "Layer" at 8196,7839 h60
  text "Name" at 8605.91,7839 h60
  text "Material" at 10015.5,7839 h60
  text "Thickness" at 10875.27,7839 h60
  text "Constant" at 11525.1,7839 h60
  text "Board Layer Stack" at 12094.97,7839 h60
  text "Board Layer Stack" at 13214.65,7839 h60
  text "1" at 8196,7719 h60
  text "Top Overlay" at 8605.91,7719 h60
  text "2" at 8196,7599 h60
  text "Top Solder" at 8605.91,7599 h60
  text "Solder Resist" at 10015.5,7599 h60
  text "0.40mil" at 10875.27,7599 h60
  text "3.5" at 11525.1,7599 h60
  text "3" at 8196,7479 h60
  text "Layer 1 - Top Layer" at 8605.91,7479 h60
  text "Copper" at 10015.5,7479 h60
  text "1.40mil" at 10875.27,7479 h60
  text "4" at 8196,7359 h60
  text "Dielectric 1" at 8605.91,7359 h60
  text "370HR" at 10015.5,7359 h60
  text "9.00mil" at 10875.27,7359 h60
  text "4.2" at 11525.1,7359 h60
  text "5" at 8196,7239 h60
  text "Layer 2 - GND" at 8605.91,7239 h60
  text "Copper" at 10015.5,7239 h60
  text "1.42mil" at 10875.27,7239 h60
  text "6" at 8196,7119 h60
  text "Dielectric 2" at 8605.91,7119 h60
  text "370HR" at 10015.5,7119 h60
  text "9.00mil" at 10875.27,7119 h60
  text "4.2" at 11525.1,7119 h60
  text "7" at 8196,6999 h60
  text "Layer 3 - PWR" at 8605.91,6999 h60
  text "Copper" at 10015.5,6999 h60
  text "1.42mil" at 10875.27,6999 h60
  text "8" at 8196,6879 h60
  text "Dielectric 3" at 8605.91,6879 h60
  text "370HR" at 10015.5,6879 h60
  text "9.00mil" at 10875.27,6879 h60
  text "4.2" at 11525.1,6879 h60
  text "9" at 8196,6759 h60
  text "Layer 4 - Bottom Layer" at 8605.91,6759 h60
  text "Copper" at 10015.5,6759 h60
  text "1.40mil" at 10875.27,6759 h60
  text "10" at 8196,6639 h60
  text "Bottom Solder" at 8605.91,6639 h60
  text "Solder Resist" at 10015.5,6639 h60
  text "0.40mil" at 10875.27,6639 h60
  text "3.5" at 11525.1,6639 h60
  text "11" at 8196,6519 h60
  text "Bottom Overlay" at 8605.91,6519 h60
  text ".Layer_Name" at 582,-858.49 h60
M13 Component Bodies Top:
  text ".Layer_Name" at 582,-858.49 h60
M14 Component Bodies Bottom:
  text ".Layer_Name" at 582,-858.49 h60
M15 Courtyards Top:
  text ".Layer_Name" at 582,-858.49 h60
M16 Courtyards Bottom:
  text ".Layer_Name" at 582,-858.49 h60
Drill Drawing:
  circle w1: c3486.5,1417.48 r24.91
  lines w1: 3461.59,196.9 3511.41,196.9 3511.41,246.72 3461.59,246.72 3461.59,196.9 ; 3461.59,358.82 3474.05,358.82 3474.05,346.36 3498.96,346.36 3498.96,358.82 3511.41,358.82 3511.41,383.73 3498.96,383.73 3498.96,396.18 3474.05,396.18 3474.05,383.73 3461.59,383.73 3461.59,358.82 ; 3461.59,495.82 3486.5,508.28 3511.41,495.82 3498.96,520.73 3511.41,545.64 3486.5,533.19 3461.59,545.64 3474.05,520.73 3461.59,495.82 ; 3461.59,657.74 3474.05,657.74 3486.5,645.28 3498.96,657.74 3511.41,657.74 3498.96,670.19 3511.41,682.64 3498.96,682.64 3486.5,695.1 3474.05,682.64 3461.59,682.64 3474.05,670.19 3461.59,657.74 ; 3461.59,819.65 3486.5,794.74 3511.41,819.65 3486.5,844.56 3461.59,819.65 ; 3461.59,994.02 3511.41,994.02 3486.5,944.2 3461.59,994.02 ; 3461.59,1093.66 3461.59,1106.11 3474.05,1118.57 3461.59,1131.02 3461.59,1143.48 3474.05,1143.48 3486.5,1131.02 3498.96,1143.48 3511.41,1143.48 3511.41,1131.02 3498.96,1118.57 3511.41,1106.11 3511.41,1093.66 3498.96,1093.66 3486.5,1106.11 3474.05,1093.66 3461.59,1093.66 ; 3461.59,1243.11 3511.41,1243.11 3511.41,1292.93 3461.59,1292.93 3461.59,1243.11 ; 3471.56,1253.08 3501.45,1253.08 3501.45,1282.97 3471.56,1282.97 3471.56,1253.08
  lines w12: 3393.7,152.07 5513.1,152.07 ; 3393.7,1497.19 5513.1,1497.19 ; 3764.37,2.61 3764.37,1646.65 ; 4121.48,2.61 4121.48,1646.65 ; 4783.49,2.61 4783.49,1646.65 ; 5067.84,2.61 5067.84,1646.65 ; 3393.7,2.61 5513.1,2.61 5513.1,1646.65 3393.7,1646.65 3393.7,2.61
  text "Symbol" at 3483.38,1542.03 h72
  text "Quantity" at 3809.21,1542.03 h72
  text "Finished Hole Size" at 4166.32,1542.03 h72
  text "Plated" at 4828.32,1542.03 h72
  text "Hole Type" at 5112.68,1542.03 h72
  text "21" at 3809.21,1392.57 h60
  text "7.87mil (0.200mm)" at 4166.32,1392.57 h60
  text "PTH" at 4828.32,1392.57 h60
  text "Round" at 5112.68,1392.57 h60
  text "323" at 3809.21,1243.11 h60
  text "10.00mil (0.254mm)" at 4166.32,1243.11 h60
  text "PTH" at 4828.32,1243.11 h60
  text "Round" at 5112.68,1243.11 h60
  text "19" at 3809.21,1093.66 h60
  text "14.96mil (0.380mm)" at 4166.32,1093.66 h60
  text "PTH" at 4828.32,1093.66 h60
  text "Round" at 5112.68,1093.66 h60
  text "10" at 3809.21,944.2 h60
  text "27.56mil (0.700mm)" at 4166.32,944.2 h60
  text "PTH" at 4828.32,944.2 h60
  text "Round" at 5112.68,944.2 h60
  text "4" at 3809.21,794.74 h60
  text "39.37mil (1.000mm)" at 4166.32,794.74 h60
  text "PTH" at 4828.32,794.74 h60
  text "Round" at 5112.68,794.74 h60
  text "17" at 3809.21,645.28 h60
  text "40.00mil (1.016mm)" at 4166.32,645.28 h60
  text "PTH" at 4828.32,645.28 h60
  text "Round" at 5112.68,645.28 h60
  text "1" at 3809.21,495.82 h60
  text "46.50mil (1.181mm)" at 4166.32,495.82 h60
  text "PTH" at 4828.32,495.82 h60
  text "Round" at 5112.68,495.82 h60
  text "1" at 3809.21,346.36 h60
  text "59.06mil (1.500mm)" at 4166.32,346.36 h60
  text "PTH" at 4828.32,346.36 h60
  text "Round" at 5112.68,346.36 h60
  text "4" at 3809.21,196.9 h60
  text "125.98mil (3.200mm)" at 4166.32,196.9 h60
  text "PTH" at 4828.32,196.9 h60
  text "Round" at 5112.68,196.9 h60
  text "400 Total" at 3809.21,47.45 h60
  text ".Layer_Name" at 582,-858.49 h60

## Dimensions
0,0 to 3000,0 on M2 Board Dimensions
5,0 to 0,2000 on M2 Board Dimensions
5,-400 to 1005,-400 on M2 Board Dimensions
